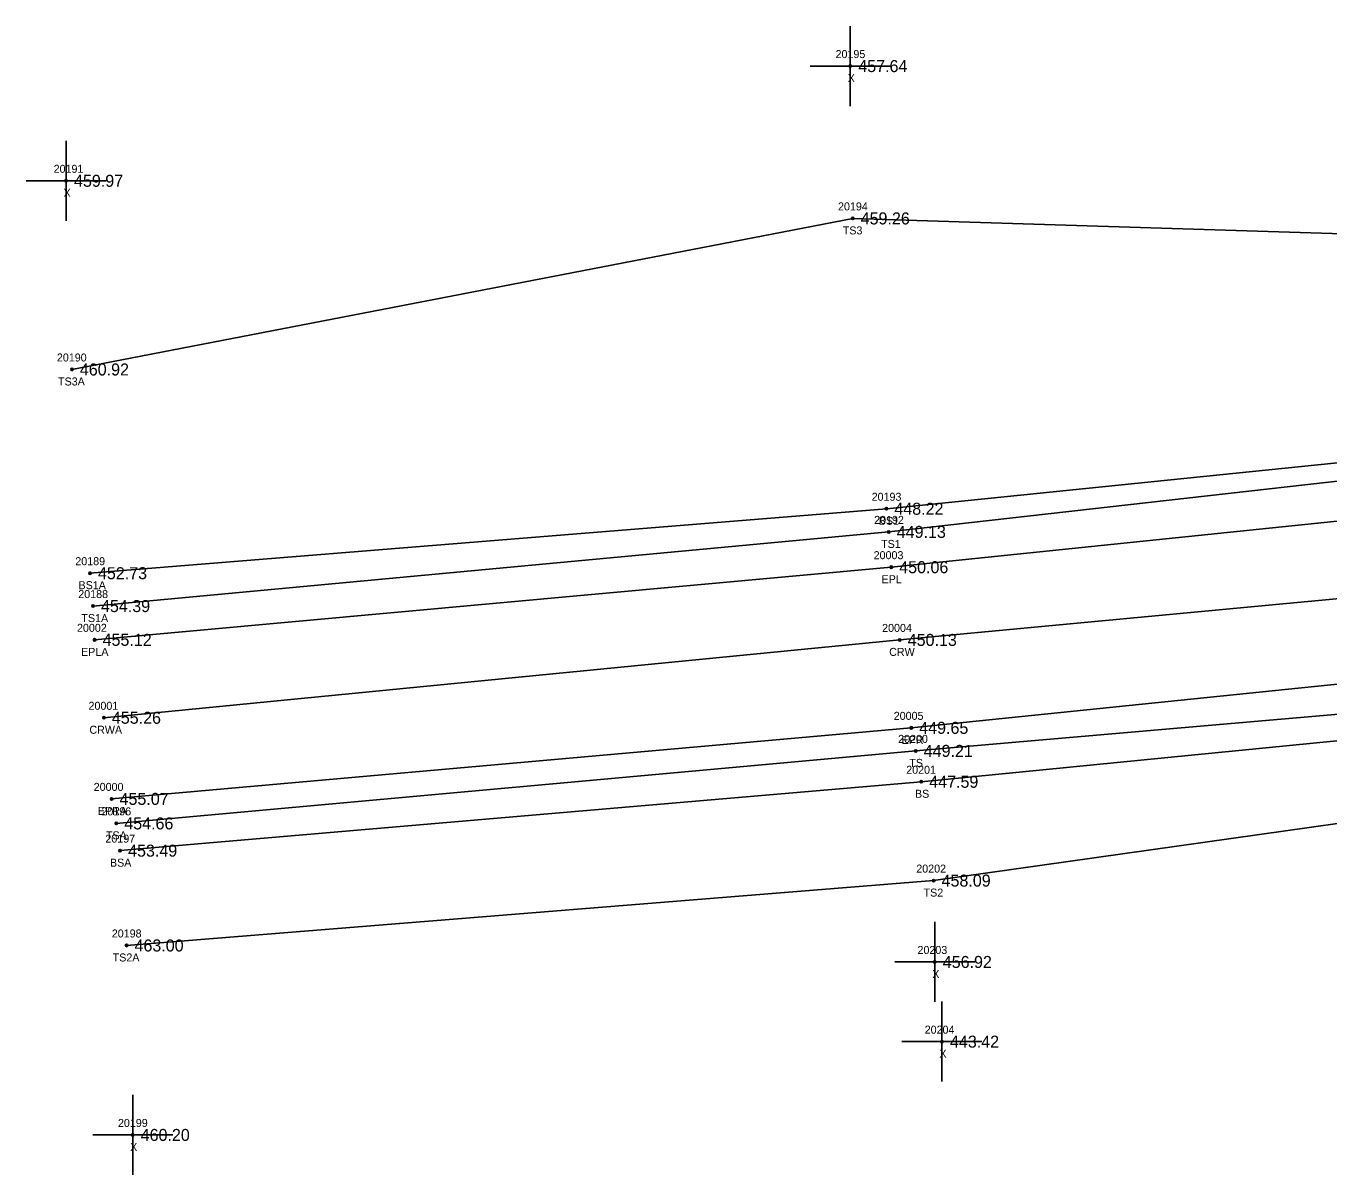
# Model space of a CAD drawing. Extents: x 1613184 to 1614731, y 770859 to 771868.
# Drawn here: x 1613183.9 to 1613346.8, y 771262.3 to 771405.9 of the extents above; entities that cross this region are included whole.
import ezdxf

# ---------------------------------------------------------------- set-up
doc = ezdxf.new("R2010")
doc.units = 0
for name, color, linetype in [('RD_DTM_BkLn1', 7, 'Continuous'), ('RD_DTM_BkLn2', 7, 'Continuous'), ('RD_DTM_BkLn_txCode', 7, 'Continuous'), ('RD_EX_Misc', 7, 'Continuous'), ('RD_EX_Misc_txCode', 7, 'Continuous'), ('RD_EX_Road', 7, 'Continuous'), ('RD_EX_Road_txCode', 7, 'Continuous'), ('RD_EX_TX_Misc_ELEV', 7, 'Continuous'), ('RD_EX_TX_Road_ELEV', 7, 'Continuous'), ('RD_HC_Survey_ELEV', 7, 'Continuous'), ('RD_HC_Survey_txCode', 7, 'Continuous'), ('RD_SMD_Locator', 7, 'Continuous')]:
    doc.layers.add(name, color=color, linetype=linetype)

msp = doc.modelspace()

# ---------------------------------------------------------------- linework, layer by layer
at = {"layer": 'RD_DTM_BkLn1'}
msp.add_lwpolyline([(1613193.64, 771319.41), (1613293.11, 771329.14), (1613392.46, 771338.5), (1613492.95, 771347.08), (1613542.61, 771350.97), (1613592.52, 771354.09), (1613642.63, 771355.86), (1613692.27, 771356.69), (1613742.08, 771356.79), (1613792.13, 771355.6), (1613841.94, 771351.86), (1613890.87, 771346.48)], dxfattribs=at)
at = {"layer": 'RD_DTM_BkLn2'}
for points in [[(1613191.9, 771337.48), (1613291.44, 771345.53), (1613389.08, 771355.5), (1613435.73, 771361.94), (1613448.05, 771379.9), (1613456.58, 771373.81), (1613489.82, 771379.95), (1613539.65, 771385.9), (1613590.16, 771390.66), (1613642.18, 771393.2), (1613691.23, 771395.53), (1613743.12, 771392.35), (1613794.87, 771390.82), (1613846.37, 771384.69), (1613895.3, 771384.28), (1613914.84, 771377.38)], [(1613189.64, 771362.94), (1613287.23, 771381.82), (1613385.74, 771378.74), (1613411.88, 771381.02)], [(1613192.28, 771333.37), (1613291.74, 771342.64), (1613389.11, 771353.66), (1613436.85, 771356.33), (1613492.16, 771363.71), (1613540.47, 771367.11), (1613591.24, 771372.7), (1613642.11, 771373.16), (1613691.12, 771373.65), (1613744.36, 771374.73), (1613793.64, 771374.02), (1613845.39, 771367.84), (1613892.43, 771366.82), (1613891.67, 771360.8)], [(1613195.19, 771306.21), (1613295.11, 771315.27), (1613393.64, 771323.81), (1613454.01, 771327.14), (1613491.18, 771327.74), (1613525.58, 771293.23)], [(1613195.67, 771302.8), (1613295.8, 771311.41), (1613393.76, 771321.05), (1613452.01, 771322.58), (1613487.68, 771317.36), (1613495.9, 771312.14), (1613522.8, 771289.94)], [(1613196.47, 771290.95), (1613297.34, 771299.06), (1613395.35, 771312.89), (1613444.76, 771319.95)]]:
    msp.add_lwpolyline(points, dxfattribs=at)
at = {"layer": 'RD_EX_Misc'}
for p, q in [((1613286.93, 771395.86), (1613286.93, 771405.86)), ((1613281.93, 771400.86), (1613291.93, 771400.86)), ((1613188.91, 771381.52), (1613188.91, 771391.52)), ((1613183.91, 771386.52), (1613193.91, 771386.52)), ((1613297.49, 771283.89), (1613297.49, 771293.89)), ((1613292.49, 771288.89), (1613302.49, 771288.89)), ((1613298.39, 771273.93), (1613298.39, 771283.93)), ((1613293.39, 771278.93), (1613303.39, 771278.93)), ((1613197.24, 771262.27), (1613197.24, 771272.27)), ((1613192.24, 771267.27), (1613202.24, 771267.27))]:
    msp.add_line(p, q, dxfattribs=at)
at = {"layer": 'RD_EX_Road'}
for points in [[(1613192.48, 771329.15), (1613292.05, 771338.23), (1613391, 771348.45), (1613492.61, 771357.17), (1613541.86, 771361.21), (1613591.56, 771364.71), (1613642.92, 771366.4), (1613692.81, 771367.35), (1613742.66, 771367.02), (1613792.19, 771365.04), (1613843.32, 771361.63), (1613887.78, 771357.57), (1613892.3, 771358.63)], [(1613194.6, 771309.27), (1613294.55, 771318.15), (1613393.75, 771328.31), (1613493.74, 771336.74), (1613544.27, 771340.57), (1613593.48, 771343.76), (1613642.77, 771345.54), (1613692.58, 771346.11), (1613741.71, 771345.82), (1613791.79, 771344.79), (1613840.79, 771341.46), (1613889.25, 771335.84)]]:
    msp.add_lwpolyline(points, dxfattribs=at)
at = {"layer": 'RD_SMD_Locator'}
for centre in [(1613286.93, 771400.86), (1613188.91, 771386.52), (1613287.23, 771381.82), (1613189.64, 771362.94), (1613291.44, 771345.53), (1613291.74, 771342.64), (1613191.9, 771337.48), (1613292.05, 771338.23), (1613192.28, 771333.37), (1613192.48, 771329.15), (1613293.11, 771329.14), (1613193.64, 771319.41), (1613294.55, 771318.15), (1613295.11, 771315.27), (1613295.8, 771311.41), (1613194.6, 771309.27), (1613195.19, 771306.21), (1613195.67, 771302.8), (1613297.34, 771299.06), (1613196.47, 771290.95), (1613297.49, 771288.89), (1613298.39, 771278.93), (1613197.24, 771267.27)]:
    msp.add_circle(centre, 0.15, dxfattribs=at)

# ---------------------------------------------------------------- texts
at = {"layer": 'RD_DTM_BkLn_txCode'}
for s, p in [('20194', (1613285.4, 771382.82)), ('TS3', (1613285.99, 771379.82)), ('20190', (1613187.77, 771363.94)), ('TS3A', (1613187.91, 771360.94)), ('20193', (1613289.6, 771346.53)), ('20192', (1613289.91, 771343.64)), ('BS1', (1613290.49, 771343.53)), ('TS1', (1613290.78, 771340.64)), ('20189', (1613190.07, 771338.48)), ('20188', (1613190.44, 771334.37)), ('BS1A', (1613190.47, 771335.48)), ('TS1A', (1613190.83, 771331.37)), ('20200', (1613292.91, 771316.27)), ('TS', (1613294.31, 771313.27)), ('20201', (1613293.92, 771312.41)), ('BS', (1613295.02, 771309.41)), ('20196', (1613193.33, 771307.21)), ('20197', (1613193.83, 771303.8)), ('TSA', (1613193.9, 771304.21)), ('BSA', (1613194.4, 771300.8)), ('20202', (1613295.18, 771300.06)), ('TS2', (1613296.09, 771297.06)), ('20198', (1613194.63, 771291.95)), ('TS2A', (1613194.74, 771288.95))]:
    msp.add_text(s, height=1, dxfattribs=at).set_placement(p)
at = {"layer": 'RD_EX_Misc_txCode'}
for s, p in [('20195', (1613285.09, 771401.86)), ('X', (1613286.61, 771398.86)), ('20191', (1613187.36, 771387.52)), ('X', (1613188.6, 771384.52)), ('20203', (1613295.33, 771289.89)), ('X', (1613297.18, 771286.89)), ('20204', (1613296.23, 771279.93)), ('X', (1613298.07, 771276.93)), ('20199', (1613195.4, 771268.27)), ('X', (1613196.92, 771265.27))]:
    msp.add_text(s, height=1, dxfattribs=at).set_placement(p)
at = {"layer": 'RD_EX_Road_txCode'}
for s, p in [('20003', (1613289.85, 771339.23)), ('EPL', (1613290.84, 771336.23)), ('20002', (1613190.28, 771330.15)), ('EPLA', (1613190.79, 771327.15)), ('20005', (1613292.36, 771319.15)), ('EPR', (1613293.33, 771316.15)), ('20000', (1613192.37, 771310.27)), ('EPRA', (1613192.89, 771307.27))]:
    msp.add_text(s, height=1, dxfattribs=at).set_placement(p)
at = {"layer": 'RD_EX_TX_Misc_ELEV'}
for s, p in [('457.64', (1613287.93, 771400.11)), ('459.97', (1613189.91, 771385.77)), ('459.26', (1613288.23, 771381.07)), ('460.92', (1613190.64, 771362.19)), ('448.22', (1613292.44, 771344.78)), ('449.13', (1613292.74, 771341.89)), ('452.73', (1613192.9, 771336.73)), ('454.39', (1613193.28, 771332.62)), ('449.21', (1613296.11, 771314.52)), ('447.59', (1613296.8, 771310.66)), ('454.66', (1613196.19, 771305.46)), ('453.49', (1613196.67, 771302.05)), ('458.09', (1613298.34, 771298.31)), ('463.00', (1613197.47, 771290.2)), ('456.92', (1613298.49, 771288.14)), ('443.42', (1613299.39, 771278.18)), ('460.20', (1613198.24, 771266.52))]:
    msp.add_text(s, height=1.5, dxfattribs=at).set_placement(p)
at = {"layer": 'RD_EX_TX_Road_ELEV'}
for s, p in [('450.06', (1613293.05, 771337.48)), ('455.12', (1613193.48, 771328.4)), ('449.65', (1613295.55, 771317.4)), ('455.07', (1613195.6, 771308.52))]:
    msp.add_text(s, height=1.5, dxfattribs=at).set_placement(p)
at = {"layer": 'RD_HC_Survey_ELEV'}
for s, p in [('450.13', (1613294.11, 771328.39)), ('455.26', (1613194.64, 771318.66))]:
    msp.add_text(s, height=1.5, dxfattribs=at).set_placement(p)
at = {"layer": 'RD_HC_Survey_txCode'}
for s, p in [('20004', (1613290.91, 771330.14)), ('CRW', (1613291.79, 771327.14)), ('20001', (1613191.72, 771320.41)), ('CRWA', (1613191.83, 771317.41))]:
    msp.add_text(s, height=1, dxfattribs=at).set_placement(p)

doc.saveas('drawing.dxf')
